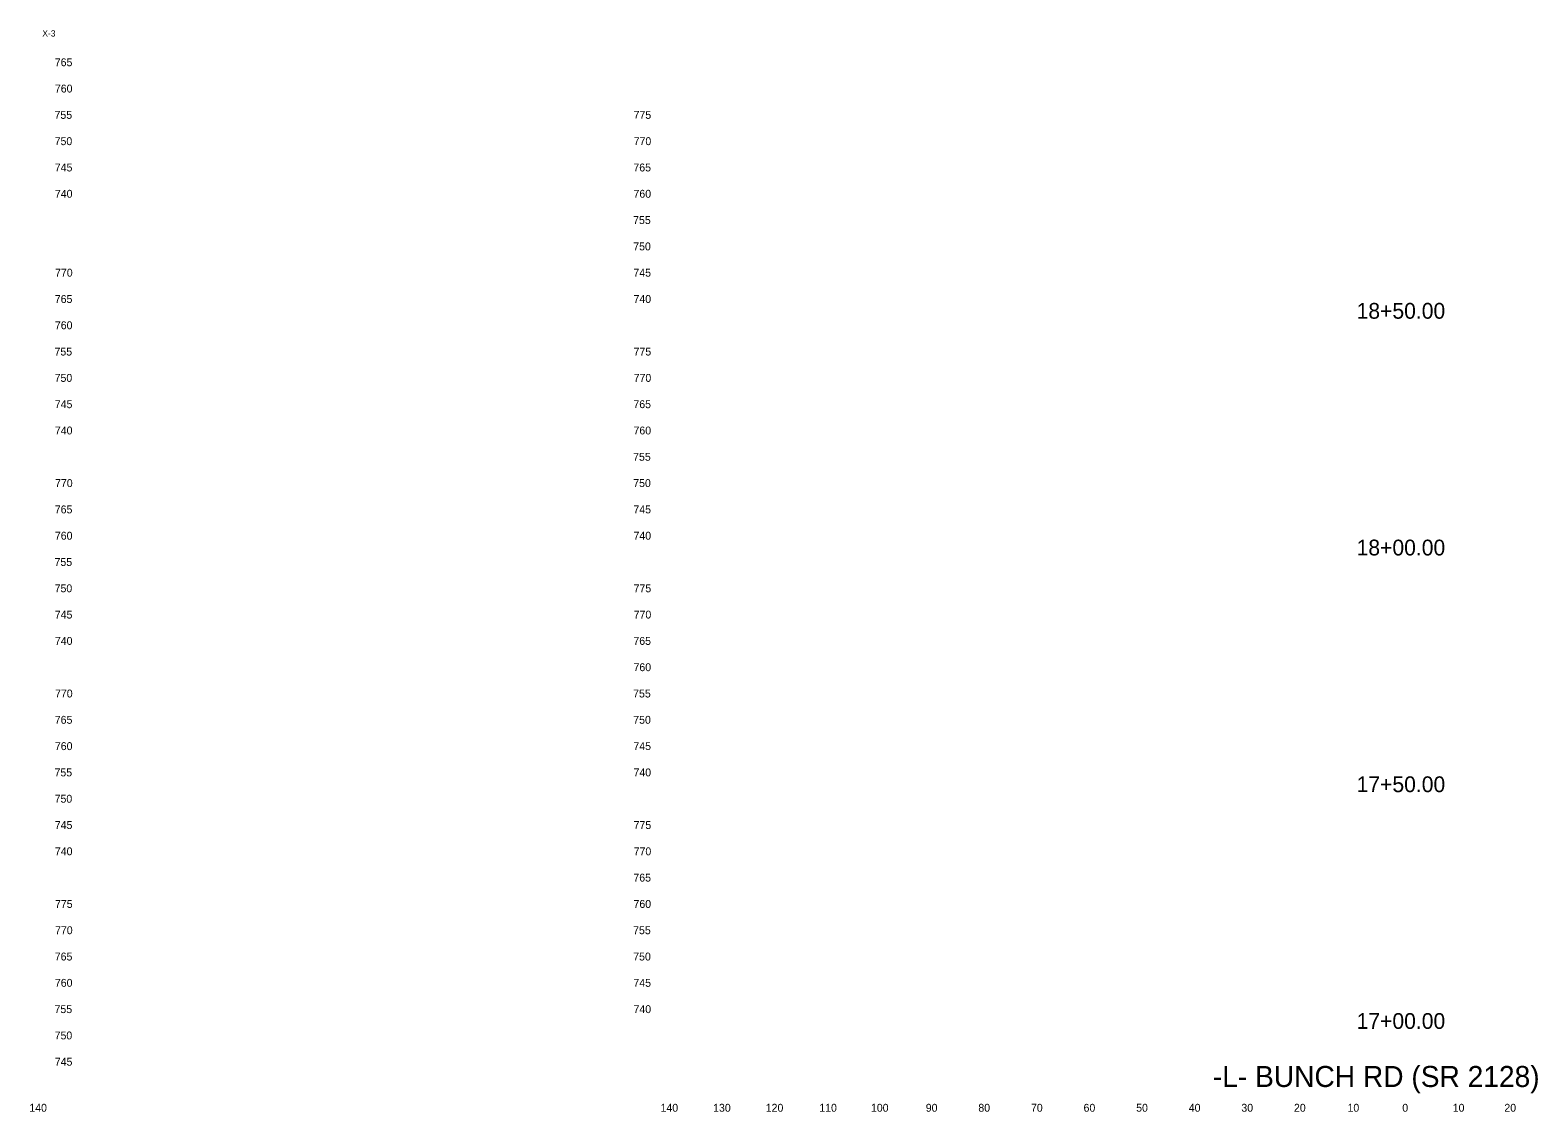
# Model space of a CAD drawing. Extents: x 2473106 to 2475402, y 633617 to 633851.
# Drawn here: x 2474594.3 to 2474880.9, y 633618.8 to 633824.4 of the extents above; entities that cross this region are included whole.
import ezdxf

# ---------------------------------------------------------------- set-up
doc = ezdxf.new("R2010")
doc.units = 0
for name, color, linetype in [('Exist Cross Section Cell', 7, 'Continuous'), ('Exist XS Center Line Elevation Label', 7, 'Continuous'), ('Exist XS Ground Line', 7, 'Continuous'), ('Prop XS SE Text', 7, 'Continuous'), ('Scratch_Level_5', 7, 'Continuous')]:
    doc.layers.add(name, color=color, linetype=linetype)

msp = doc.modelspace()

# ---------------------------------------------------------------- texts
at = {"layer": 'Exist Cross Section Cell'}
for s, p in [('140', (2474594.13, 633618.82)), ('140', (2474714.13, 633618.82)), ('130', (2474724.13, 633618.82)), ('120', (2474734.13, 633618.82)), ('110', (2474744.31, 633618.82)), ('100', (2474754.13, 633618.82)), ('90', (2474764.55, 633618.82)), ('80', (2474774.55, 633618.82)), ('70', (2474784.55, 633618.82)), ('60', (2474794.55, 633618.82)), ('50', (2474804.55, 633618.82)), ('40', (2474814.55, 633618.82)), ('30', (2474824.55, 633618.82)), ('20', (2474834.55, 633618.82)), ('10', (2474844.73, 633618.82)), ('0', (2474855.14, 633618.82)), ('0', (2474855.14, 633618.82)), ('10', (2474864.73, 633618.82)), ('20', (2474874.55, 633618.82))]:
    msp.add_text(s, height=1.5, dxfattribs=at).set_placement(p)
at = {"layer": 'Exist XS Center Line Elevation Label'}
for s, p in [('18+50.00', (2474846.46, 633769.57)), ('18+00.00', (2474846.46, 633724.57)), ('17+50.00', (2474846.46, 633679.57)), ('17+00.00', (2474846.46, 633634.57))]:
    msp.add_text(s, height=3, dxfattribs=at).set_placement(p)
at = {"layer": 'Exist XS Ground Line'}
for s, p in [('765', (2474598.97, 633817.57)), ('760', (2474598.99, 633812.57)), ('755', (2474598.92, 633807.57)), ('775', (2474709.01, 633807.57)), ('750', (2474598.94, 633802.57)), ('770', (2474709.02, 633802.57)), ('745', (2474598.97, 633797.57)), ('765', (2474708.97, 633797.57)), ('740', (2474598.99, 633792.57)), ('760', (2474708.99, 633792.57)), ('755', (2474708.92, 633787.57)), ('750', (2474708.94, 633782.57)), ('770', (2474599.02, 633777.57)), ('745', (2474708.97, 633777.57)), ('765', (2474598.97, 633772.57)), ('740', (2474708.99, 633772.57)), ('760', (2474598.99, 633767.57)), ('755', (2474598.92, 633762.57)), ('775', (2474709.01, 633762.57)), ('750', (2474598.94, 633757.57)), ('770', (2474709.02, 633757.57)), ('745', (2474598.97, 633752.57)), ('765', (2474708.97, 633752.57)), ('740', (2474598.99, 633747.57)), ('760', (2474708.99, 633747.57)), ('755', (2474708.92, 633742.57)), ('770', (2474599.02, 633737.57)), ('750', (2474708.94, 633737.57)), ('765', (2474598.97, 633732.57)), ('745', (2474708.97, 633732.57)), ('760', (2474598.99, 633727.57)), ('740', (2474708.99, 633727.57)), ('755', (2474598.92, 633722.57)), ('750', (2474598.94, 633717.57)), ('775', (2474709.01, 633717.57)), ('745', (2474598.97, 633712.57)), ('770', (2474709.02, 633712.57)), ('740', (2474598.99, 633707.57)), ('765', (2474708.97, 633707.57)), ('760', (2474708.99, 633702.57)), ('770', (2474599.02, 633697.57)), ('755', (2474708.92, 633697.57)), ('765', (2474598.97, 633692.57)), ('750', (2474708.94, 633692.57)), ('760', (2474598.99, 633687.57)), ('745', (2474708.97, 633687.57)), ('755', (2474598.92, 633682.57)), ('740', (2474708.99, 633682.57)), ('750', (2474598.94, 633677.57)), ('745', (2474598.97, 633672.57)), ('775', (2474709.01, 633672.57)), ('740', (2474598.99, 633667.57)), ('770', (2474709.02, 633667.57)), ('765', (2474708.97, 633662.57)), ('775', (2474599.01, 633657.57)), ('760', (2474708.99, 633657.57)), ('770', (2474599.02, 633652.57)), ('755', (2474708.92, 633652.57)), ('765', (2474598.97, 633647.57)), ('750', (2474708.94, 633647.57)), ('760', (2474598.99, 633642.57)), ('745', (2474708.97, 633642.57)), ('755', (2474598.92, 633637.57)), ('740', (2474708.99, 633637.57)), ('750', (2474598.94, 633632.57)), ('745', (2474598.97, 633627.57))]:
    msp.add_text(s, height=1.5, dxfattribs=at).set_placement(p)
at = {"layer": 'Prop XS SE Text'}
msp.add_text('X-3', height=1.2, dxfattribs=at).set_placement((2474596.61, 633823.21))
at = {"layer": 'Scratch_Level_5'}
msp.add_text('-L- BUNCH RD (SR 2128)', height=4, dxfattribs=at).set_placement((2474819.13, 633623.52))

doc.saveas('drawing.dxf')
